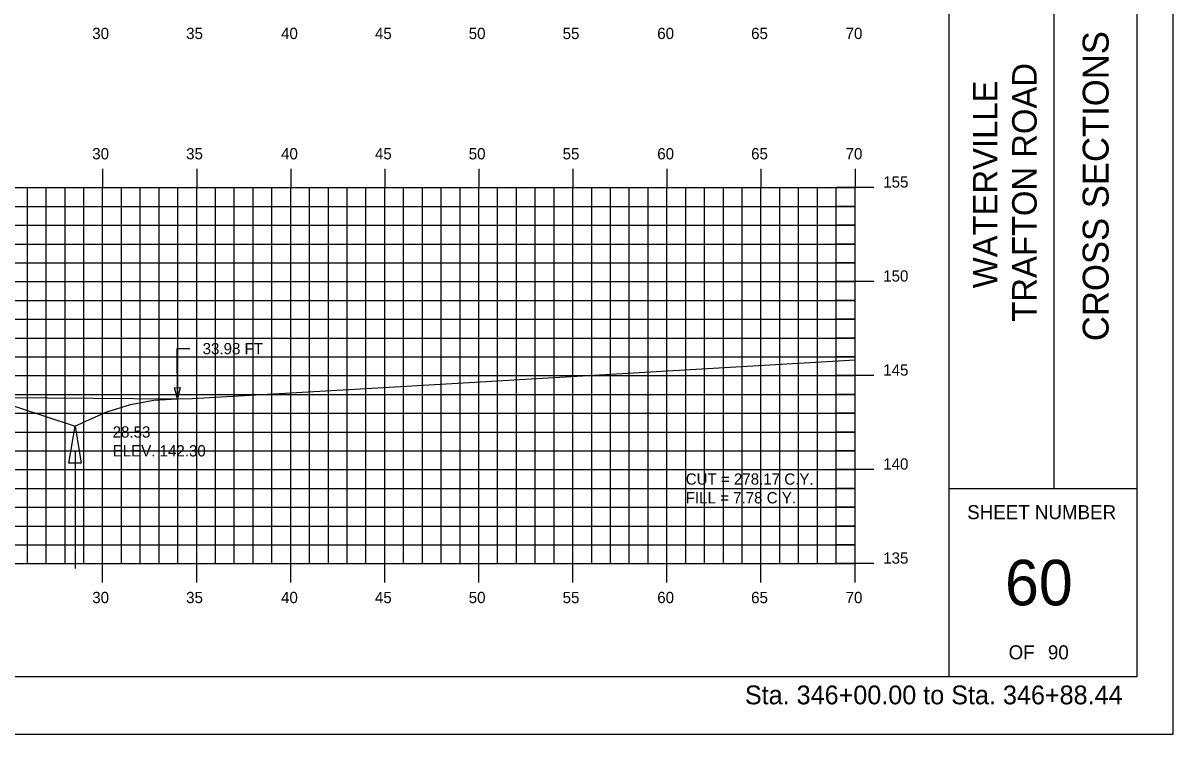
# Model space of a CAD drawing. Extents: x 1143863 to 1144033, y 608981 to 609091.
# Drawn here: x 1143972.4 to 1144033.5, y 608981.3 to 609019.1 of the extents above; entities that cross this region are included whole.
import ezdxf

# ---------------------------------------------------------------- set-up
doc = ezdxf.new("R2010")
doc.units = 0
for name, color, linetype in [('BORDER', 7, 'Continuous'), ('D_Drainage_Ditch_Line', 7, 'Continuous'), ('D_Roadway_SlopeLines', 7, 'Continuous'), ('D_Text_Standard', 7, 'Continuous'), ('H_V ANNOTATION', 7, 'Continuous'), ('HIGHWAY_TITLE', 7, 'Continuous'), ('MAJOR', 7, 'Continuous'), ('MINOR', 7, 'Continuous'), ('PLOT BOUNDARY', 7, 'Continuous'), ('S_Roadway_Centerline', 7, 'Continuous')]:
    doc.layers.add(name, color=color, linetype=linetype)

msp = doc.modelspace()

# ---------------------------------------------------------------- linework, layer by layer
msp.add_lwpolyline([(1143914.516, 608999.356), (1143915.766, 608999.394), (1143917.016, 608999.242), (1143918.266, 608998.902), (1143919.516, 608998.371), (1143920.868, 608997.695), (1143923.868, 608998.695), (1143931.592, 609001.27), (1143931.593, 609001.27), (1143935.593, 609001.43), (1143946.593, 609001.65), (1143957.593, 609001.43), (1143964.593, 609001.15), (1143972.125, 608998.639), (1143975.125, 608997.639), (1143975.57, 608997.862), (1143976.82, 608998.408), (1143978.07, 608998.795), (1143979.32, 608999.024), (1143980.57, 608999.095)])
at = {"layer": 'BORDER'}
for p, q in [((1144021.593, 608984.335), (1144021.593, 609089.335)), ((1144027.184, 608994.338), (1144027.184, 609029.338)), ((1144021.593, 608994.338), (1144031.593, 608994.338))]:
    msp.add_line(p, q, dxfattribs=at)
msp.add_lwpolyline([(1143871.593, 608984.335), (1144031.593, 608984.335), (1144031.593, 609089.335), (1143871.593, 609089.335)], close=True, dxfattribs=at)
at = {"layer": 'D_Drainage_Ditch_Line'}
msp.add_line((1143975.125, 608996.327), (1143975.124, 608990.083), dxfattribs=at)
msp.add_lwpolyline([(1143975.453, 608995.671), (1143974.797, 608995.671), (1143975.125, 608997.639)], close=True, dxfattribs=at)
at = {"layer": 'D_Roadway_SlopeLines'}
for points in [[(1143975.125, 608997.639), (1143975.57, 608997.862), (1143976.82, 608998.408), (1143978.07, 608998.795), (1143979.32, 608999.024), (1143980.57, 608999.095)], [(1143972.125, 608998.639), (1143975.125, 608997.639)]]:
    msp.add_lwpolyline(points, dxfattribs=at)
at = {"layer": 'D_Text_Standard'}
msp.add_lwpolyline([(1143980.57, 608999.112), (1143980.548, 609001.77), (1143981.228, 609001.77)], dxfattribs=at)
msp.add_lwpolyline([(1143980.57, 608999.112), (1143980.42, 608999.693), (1143980.711, 608999.695)], close=True, dxfattribs=at)
at = {"layer": 'MAJOR'}
for p, q in [((1143976.593, 609011.337), (1143976.593, 609010.335)), ((1143981.593, 609011.337), (1143981.593, 609010.335)), ((1143986.593, 609011.337), (1143986.593, 609010.335)), ((1143991.593, 609011.337), (1143991.593, 609010.335)), ((1143996.593, 609011.337), (1143996.593, 609010.335)), ((1144001.593, 609011.337), (1144001.593, 609010.335)), ((1144006.593, 609011.337), (1144006.593, 609010.335)), ((1144011.593, 609011.337), (1144011.593, 609010.335)), ((1144016.593, 609011.337), (1144016.593, 609010.335)), ((1143876.593, 609010.335), (1144016.593, 609010.335)), ((1143876.593, 609010.335), (1144016.593, 609010.335)), ((1143976.593, 608990.335), (1143976.593, 609010.335)), ((1143981.593, 608990.335), (1143981.593, 609010.335)), ((1143986.593, 608990.335), (1143986.593, 609010.335)), ((1143991.593, 608990.335), (1143991.593, 609010.335)), ((1143996.593, 608990.335), (1143996.593, 609010.335)), ((1144001.593, 608990.335), (1144001.593, 609010.335)), ((1144006.593, 608990.335), (1144006.593, 609010.335)), ((1144011.593, 608990.335), (1144011.593, 609010.335)), ((1144017.595, 609010.335), (1144015.591, 609010.335)), ((1144016.593, 608990.335), (1144016.593, 609010.335)), ((1144016.593, 608990.335), (1144016.593, 609010.335)), ((1143876.593, 609005.335), (1144016.593, 609005.335)), ((1144017.595, 609005.335), (1144015.591, 609005.335)), ((1143876.593, 609000.335), (1144016.593, 609000.335)), ((1144017.595, 609000.335), (1144015.591, 609000.335)), ((1143876.593, 608995.335), (1144016.593, 608995.335)), ((1144017.595, 608995.335), (1144015.591, 608995.335)), ((1143876.593, 608990.335), (1144016.593, 608990.335)), ((1143876.593, 608990.335), (1144016.593, 608990.335)), ((1143976.593, 608989.333), (1143976.593, 608990.335)), ((1143981.593, 608989.333), (1143981.593, 608990.335)), ((1143986.593, 608989.333), (1143986.593, 608990.335)), ((1143991.593, 608989.333), (1143991.593, 608990.335)), ((1143996.593, 608989.333), (1143996.593, 608990.335)), ((1144001.593, 608989.333), (1144001.593, 608990.335)), ((1144006.593, 608989.333), (1144006.593, 608990.335)), ((1144011.593, 608989.333), (1144011.593, 608990.335)), ((1144017.595, 608990.335), (1144015.591, 608990.335)), ((1144016.593, 608989.333), (1144016.593, 608990.335))]:
    msp.add_line(p, q, dxfattribs=at)
at = {"layer": 'MINOR'}
for p, q in [((1143972.593, 608990.335), (1143972.593, 609010.335)), ((1143973.593, 608990.335), (1143973.593, 609010.335)), ((1143974.593, 608990.335), (1143974.593, 609010.335)), ((1143975.593, 608990.335), (1143975.593, 609010.335)), ((1143977.593, 608990.335), (1143977.593, 609010.335)), ((1143978.593, 608990.335), (1143978.593, 609010.335)), ((1143979.593, 608990.335), (1143979.593, 609010.335)), ((1143980.593, 608990.335), (1143980.593, 609010.335)), ((1143982.593, 608990.335), (1143982.593, 609010.335)), ((1143983.593, 608990.335), (1143983.593, 609010.335)), ((1143984.593, 608990.335), (1143984.593, 609010.335)), ((1143985.593, 608990.335), (1143985.593, 609010.335)), ((1143987.593, 608990.335), (1143987.593, 609010.335)), ((1143988.593, 608990.335), (1143988.593, 609010.335)), ((1143989.593, 608990.335), (1143989.593, 609010.335)), ((1143990.593, 608990.335), (1143990.593, 609010.335)), ((1143992.593, 608990.335), (1143992.593, 609010.335)), ((1143993.593, 608990.335), (1143993.593, 609010.335)), ((1143994.593, 608990.335), (1143994.593, 609010.335)), ((1143995.593, 608990.335), (1143995.593, 609010.335)), ((1143997.593, 608990.335), (1143997.593, 609010.335)), ((1143998.593, 608990.335), (1143998.593, 609010.335)), ((1143999.593, 608990.335), (1143999.593, 609010.335)), ((1144000.593, 608990.335), (1144000.593, 609010.335)), ((1144002.593, 608990.335), (1144002.593, 609010.335)), ((1144003.593, 608990.335), (1144003.593, 609010.335)), ((1144004.593, 608990.335), (1144004.593, 609010.335)), ((1144005.593, 608990.335), (1144005.593, 609010.335)), ((1144007.593, 608990.335), (1144007.593, 609010.335)), ((1144008.593, 608990.335), (1144008.593, 609010.335)), ((1144009.593, 608990.335), (1144009.593, 609010.335)), ((1144010.593, 608990.335), (1144010.593, 609010.335)), ((1144012.593, 608990.335), (1144012.593, 609010.335)), ((1144013.593, 608990.335), (1144013.593, 609010.335)), ((1144014.593, 608990.335), (1144014.593, 609010.335)), ((1144015.593, 608990.335), (1144015.593, 609010.335)), ((1143876.593, 609009.335), (1144016.593, 609009.335)), ((1144016.593, 609009.335), (1144015.591, 609009.335)), ((1143876.593, 609008.335), (1144016.593, 609008.335)), ((1144016.593, 609008.335), (1144015.591, 609008.335)), ((1143876.593, 609007.335), (1144016.593, 609007.335)), ((1144016.593, 609007.335), (1144015.591, 609007.335)), ((1143876.593, 609006.335), (1144016.593, 609006.335)), ((1144016.593, 609006.335), (1144015.591, 609006.335)), ((1143876.593, 609004.335), (1144016.593, 609004.335)), ((1144016.593, 609004.335), (1144015.591, 609004.335)), ((1143876.593, 609003.335), (1144016.593, 609003.335)), ((1144016.593, 609003.335), (1144015.591, 609003.335)), ((1143876.593, 609002.335), (1144016.593, 609002.335)), ((1144016.593, 609002.335), (1144015.591, 609002.335)), ((1143876.593, 609001.335), (1144016.593, 609001.335)), ((1144016.593, 609001.335), (1144015.591, 609001.335)), ((1143876.593, 608999.335), (1144016.593, 608999.335)), ((1144016.593, 608999.335), (1144015.591, 608999.335)), ((1143876.593, 608998.335), (1144016.593, 608998.335)), ((1144016.593, 608998.335), (1144015.591, 608998.335)), ((1143876.593, 608997.335), (1144016.593, 608997.335)), ((1144016.593, 608997.335), (1144015.591, 608997.335)), ((1143876.593, 608996.335), (1144016.593, 608996.335)), ((1144016.593, 608996.335), (1144015.591, 608996.335)), ((1143876.593, 608994.335), (1144016.593, 608994.335)), ((1144016.593, 608994.335), (1144015.591, 608994.335)), ((1143876.593, 608993.335), (1144016.593, 608993.335)), ((1144016.593, 608993.335), (1144015.591, 608993.335)), ((1143876.593, 608992.335), (1144016.593, 608992.335)), ((1144016.593, 608992.335), (1144015.591, 608992.335)), ((1143876.593, 608991.335), (1144016.593, 608991.335)), ((1144016.593, 608991.335), (1144015.591, 608991.335))]:
    msp.add_line(p, q, dxfattribs=at)
at = {"layer": 'PLOT BOUNDARY'}
msp.add_lwpolyline([(1143863.5, 608981.276), (1144033.5, 608981.276), (1144033.5, 609091.276), (1143863.5, 609091.276)], close=True, dxfattribs=at)
at = {"layer": 'S_Roadway_Centerline'}
msp.add_lwpolyline([(1143966.29, 608999.203), (1143976.108, 608999.128), (1143980.451, 608999.093), (1143981.347, 608999.111), (1143991.529, 608999.708), (1144016.593, 609001.18)], dxfattribs=at)

# ---------------------------------------------------------------- texts
at = {"layer": 'BORDER'}
msp.add_text('CROSS SECTIONS', height=1.37787, rotation=90, dxfattribs=at).set_placement((1144030.077, 609002.172))
for s, height, p in [('SHEET NUMBER', 0.74527, (1144022.558, 608992.701)), ('60', 2.4194, (1144024.569, 608988.118)), ('OF', 0.7453, (1144024.76, 608985.248)), ('90', 0.7453, (1144026.849, 608985.248))]:
    msp.add_text(s, height=height, dxfattribs=at).set_placement(p)
at = {"layer": 'D_Text_Standard'}
for s, p in [('33.98 FT', (1143981.908, 609001.47)), ('28.53', (1143977.125, 608997.039)), ('ELEV. 142.30', (1143977.125, 608996.037)), ('CUT = 278.17 C.Y.', (1144007.593, 608994.535)), ('FILL = 7.78 C.Y.', (1144007.593, 608993.539))]:
    msp.add_text(s, height=0.6, dxfattribs=at).set_placement(p)
at = {"layer": 'H_V ANNOTATION'}
for s, height, p in [('30', 0.6, (1143976.041, 609018.235)), ('35', 0.6, (1143981.033, 609018.235)), ('40', 0.6, (1143986.079, 609018.235)), ('45', 0.6, (1143991.071, 609018.235)), ('50', 0.6, (1143996.057, 609018.235)), ('55', 0.6, (1144001.049, 609018.235)), ('60', 0.6, (1144006.079, 609018.235)), ('65', 0.6, (1144011.071, 609018.235)), ('70', 0.6, (1144016.095, 609018.235)), ('30', 0.6, (1143976.041, 609011.835)), ('35', 0.6, (1143981.033, 609011.835)), ('40', 0.6, (1143986.079, 609011.835)), ('45', 0.6, (1143991.071, 609011.835)), ('50', 0.6, (1143996.057, 609011.835)), ('55', 0.6, (1144001.049, 609011.835)), ('60', 0.6, (1144006.079, 609011.835)), ('65', 0.6, (1144011.071, 609011.835)), ('70', 0.6, (1144016.095, 609011.835)), ('155', 0.6, (1144018.093, 609010.335)), ('150', 0.6, (1144018.093, 609005.335)), ('145', 0.6, (1144018.093, 609000.335)), ('140', 0.6, (1144018.093, 608995.335)), ('135', 0.6, (1144018.093, 608990.335)), ('30', 0.6, (1143976.041, 608988.235)), ('35', 0.6, (1143981.033, 608988.235)), ('40', 0.6, (1143986.079, 608988.235)), ('45', 0.6, (1143991.071, 608988.235)), ('50', 0.6, (1143996.057, 608988.235)), ('55', 0.6, (1144001.049, 608988.235)), ('60', 0.6, (1144006.079, 608988.235)), ('65', 0.6, (1144011.071, 608988.235)), ('70', 0.6, (1144016.095, 608988.235)), ('Sta. 346+00.00 to Sta. 346+88.44', 1.0002, (1144010.739, 608982.855))]:
    msp.add_text(s, height=height, dxfattribs=at).set_placement(p)
at = {"layer": 'HIGHWAY_TITLE'}
for s, height, p in [('TRAFTON ROAD', 1.30428, (1144026.252, 609003.201)), ('WATERVILLE', 1.3043, (1144024.165, 609004.98))]:
    msp.add_text(s, height=height, rotation=90, dxfattribs=at).set_placement(p)

doc.saveas('drawing.dxf')
